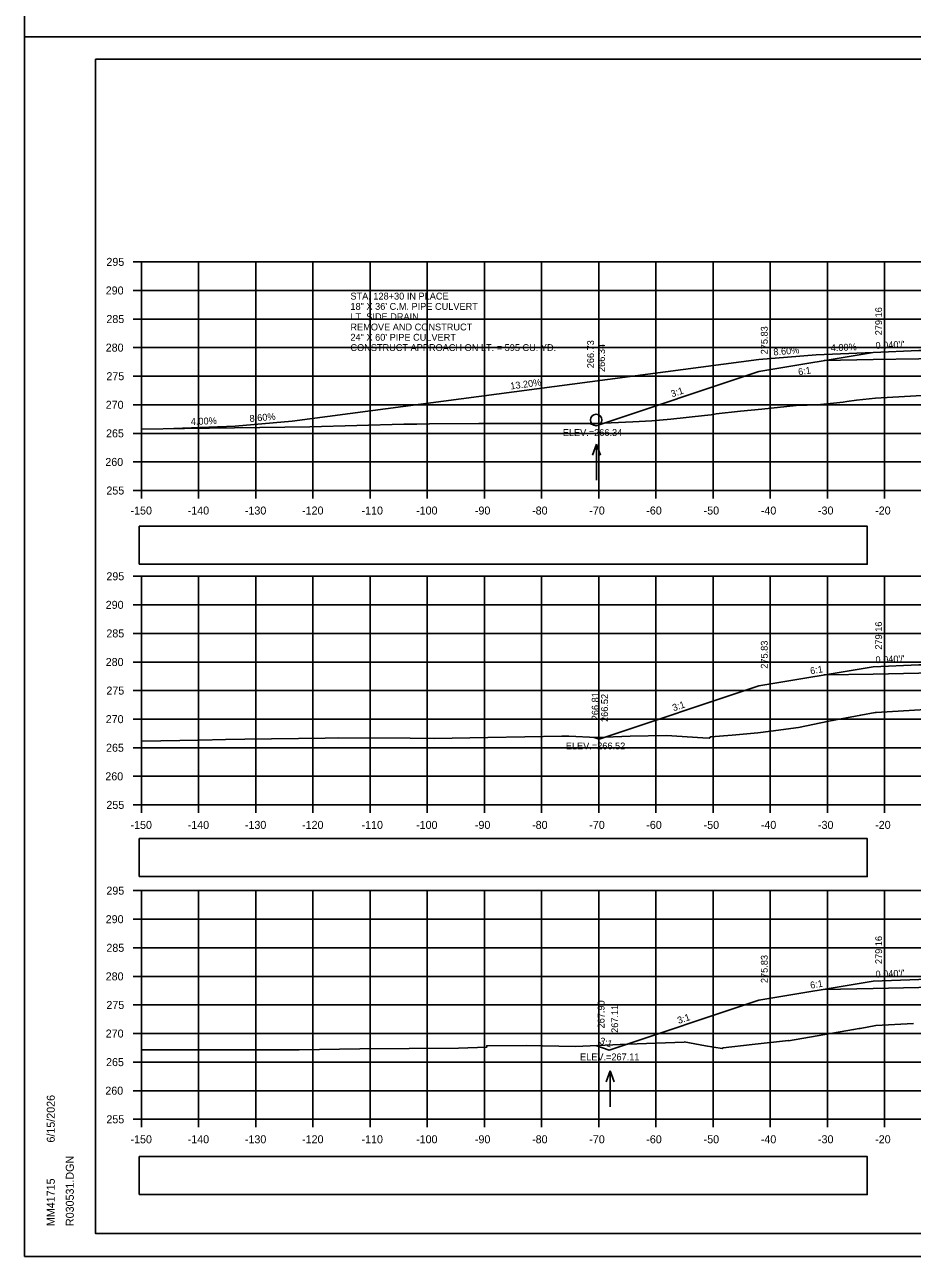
# Model space of a CAD drawing. Extents: x 285 to 4233, y -659 to 3710.
# Drawn here: x 368.9 to 524.1, y 1469.5 to 1685 of the extents above; entities that cross this region are included whole.
import ezdxf

# ---------------------------------------------------------------- set-up
doc = ezdxf.new("R2010")
doc.units = 0
for name, color, linetype in [('R_Alt Surface', 7, 'Continuous'), ('R_Axis', 7, 'Continuous'), ('R_Axis Annot', 7, 'Continuous'), ('R_Border', 7, 'Continuous'), ('R_Drive', 7, 'Continuous'), ('R_Exist Surface', 7, 'Continuous'), ('R_Fin Surface', 7, 'Continuous'), ('R_Grid', 7, 'Continuous'), ('R_No Plot', 7, 'Continuous'), ('R_Water', 7, 'Continuous'), ('R_Water Annot', 7, 'Continuous'), ('R_Xsect Elev', 7, 'Continuous'), ('R_Xsect Slope', 7, 'Continuous')]:
    doc.layers.add(name, color=color, linetype=linetype)

msp = doc.modelspace()

# ---------------------------------------------------------------- linework, layer by layer
at = {"layer": 'R_Alt Surface'}
for points in [[(508.71, 1626.25), (517.28, 1626.42), (525.28, 1626.58), (551.28, 1627.1), (551.28, 1627.1), (557.28, 1626.98), (566.12, 1626.8)], [(508.71, 1571.25), (517.28, 1571.42), (525.28, 1571.58), (551.28, 1572.1), (551.28, 1572.1), (557.28, 1571.98), (566.12, 1571.8)], [(508.71, 1516.25), (517.28, 1516.42), (525.28, 1516.58), (551.28, 1517.1), (551.28, 1517.1), (557.28, 1516.98), (566.12, 1516.8)]]:
    msp.add_lwpolyline(points, dxfattribs=at)
at = {"layer": 'R_Axis'}
for p, q in [((387.88, 1643.52), (389.28, 1643.52)), ((389.28, 1603.52), (389.28, 1643.52)), ((387.88, 1638.52), (389.28, 1638.52)), ((387.88, 1633.52), (389.28, 1633.52)), ((387.88, 1628.52), (389.28, 1628.52)), ((387.88, 1623.52), (389.28, 1623.52)), ((387.88, 1618.52), (389.28, 1618.52)), ((387.88, 1613.52), (389.28, 1613.52)), ((387.88, 1608.52), (389.28, 1608.52)), ((387.88, 1603.52), (389.28, 1603.52)), ((389.28, 1603.52), (689.28, 1603.52)), ((389.28, 1602.12), (389.28, 1603.52)), ((399.28, 1602.12), (399.28, 1603.52)), ((409.28, 1602.12), (409.28, 1603.52)), ((419.28, 1602.12), (419.28, 1603.52)), ((429.28, 1602.12), (429.28, 1603.52)), ((439.28, 1602.12), (439.28, 1603.52)), ((449.28, 1602.12), (449.28, 1603.52)), ((459.28, 1602.12), (459.28, 1603.52)), ((469.28, 1602.12), (469.28, 1603.52)), ((479.28, 1602.12), (479.28, 1603.52)), ((489.28, 1602.12), (489.28, 1603.52)), ((499.28, 1602.12), (499.28, 1603.52)), ((509.28, 1602.12), (509.28, 1603.52)), ((519.28, 1602.12), (519.28, 1603.52)), ((387.88, 1588.52), (389.28, 1588.52)), ((389.28, 1548.52), (389.28, 1588.52)), ((387.88, 1583.52), (389.28, 1583.52)), ((387.88, 1578.52), (389.28, 1578.52)), ((387.88, 1573.52), (389.28, 1573.52)), ((387.88, 1568.52), (389.28, 1568.52)), ((387.88, 1563.52), (389.28, 1563.52)), ((387.88, 1558.52), (389.28, 1558.52)), ((387.88, 1553.52), (389.28, 1553.52)), ((387.88, 1548.52), (389.28, 1548.52)), ((389.28, 1548.52), (689.28, 1548.52)), ((389.28, 1547.12), (389.28, 1548.52)), ((399.28, 1547.12), (399.28, 1548.52)), ((409.28, 1547.12), (409.28, 1548.52)), ((419.28, 1547.12), (419.28, 1548.52)), ((429.28, 1547.12), (429.28, 1548.52)), ((439.28, 1547.12), (439.28, 1548.52)), ((449.28, 1547.12), (449.28, 1548.52)), ((459.28, 1547.12), (459.28, 1548.52)), ((469.28, 1547.12), (469.28, 1548.52)), ((479.28, 1547.12), (479.28, 1548.52)), ((489.28, 1547.12), (489.28, 1548.52)), ((499.28, 1547.12), (499.28, 1548.52)), ((509.28, 1547.12), (509.28, 1548.52)), ((519.28, 1547.12), (519.28, 1548.52)), ((387.88, 1533.52), (389.28, 1533.52)), ((389.28, 1493.52), (389.28, 1533.52)), ((387.88, 1528.52), (389.28, 1528.52)), ((387.88, 1523.52), (389.28, 1523.52)), ((387.88, 1518.52), (389.28, 1518.52)), ((387.88, 1513.52), (389.28, 1513.52)), ((387.88, 1508.52), (389.28, 1508.52)), ((387.88, 1503.52), (389.28, 1503.52)), ((387.88, 1498.52), (389.28, 1498.52)), ((387.88, 1493.52), (389.28, 1493.52)), ((389.28, 1493.52), (689.28, 1493.52)), ((389.28, 1492.12), (389.28, 1493.52)), ((399.28, 1492.12), (399.28, 1493.52)), ((409.28, 1492.12), (409.28, 1493.52)), ((419.28, 1492.12), (419.28, 1493.52)), ((429.28, 1492.12), (429.28, 1493.52)), ((439.28, 1492.12), (439.28, 1493.52)), ((449.28, 1492.12), (449.28, 1493.52)), ((459.28, 1492.12), (459.28, 1493.52)), ((469.28, 1492.12), (469.28, 1493.52)), ((479.28, 1492.12), (479.28, 1493.52)), ((489.28, 1492.12), (489.28, 1493.52)), ((499.28, 1492.12), (499.28, 1493.52)), ((509.28, 1492.12), (509.28, 1493.52)), ((519.28, 1492.12), (519.28, 1493.52))]:
    msp.add_line(p, q, dxfattribs=at)
at = {"layer": 'R_Axis Annot'}
for points in [[(388.91, 1590.62), (516.24, 1590.62), (516.24, 1597.27), (388.91, 1597.27)], [(388.91, 1535.98), (516.24, 1535.98), (516.24, 1542.63), (388.91, 1542.63)], [(388.91, 1480.34), (516.24, 1480.34), (516.24, 1486.99), (388.91, 1486.99)]]:
    msp.add_lwpolyline(points, close=True, dxfattribs=at)
at = {"layer": 'R_Border'}
for p, q in [((381.28, 1678.98), (697.46, 1678.98)), ((381.28, 1473.52), (381.28, 1678.98)), ((381.28, 1473.52), (381.28, 1473.52)), ((697.46, 1473.52), (381.28, 1473.52))]:
    msp.add_line(p, q, dxfattribs=at)
at = {"layer": 'R_Drive'}
for p, q in [((507.28, 1627.28), (497.28, 1626.42)), ((517.28, 1627.68), (507.28, 1627.28)), ((497.28, 1626.42), (415.67, 1615.65)), ((405.67, 1614.79), (394.96, 1614.36)), ((415.67, 1615.65), (405.67, 1614.79))]:
    msp.add_line(p, q, dxfattribs=at)
at = {"layer": 'R_Exist Surface'}
for points in [[(389.28, 1614.28), (396.85, 1614.38), (418.73, 1614.66), (435.21, 1615.12), (437.44, 1615.14), (439.7, 1615.17), (448.33, 1615.26), (458.76, 1615.22), (467.05, 1615.24), (468.95, 1615.26), (475.23, 1615.54), (478.58, 1615.7), (481.91, 1616), (487.79, 1616.64), (488.94, 1616.77), (489.84, 1616.92), (494.07, 1617.39), (497.8, 1617.77), (503.8, 1618.37), (507.68, 1618.54), (508.07, 1618.56), (512, 1618.97), (512.69, 1619.09), (514.35, 1619.31), (517.66, 1619.7), (517.67, 1619.7), (517.68, 1619.7), (526.81, 1620.22)], [(389.28, 1559.67), (399.38, 1559.85), (404.02, 1559.98), (407.39, 1560.02), (421.43, 1560.21), (423.74, 1560.23), (436.27, 1560.22), (440.47, 1560.14), (449.89, 1560.33), (462.85, 1560.57), (463.55, 1560.56), (464.06, 1560.55), (468.87, 1560.31), (474.8, 1560.54), (481.13, 1560.65), (487.47, 1560.23), (488.59, 1560.17), (488.67, 1560.24), (488.9, 1560.45), (492.6, 1560.71), (497.08, 1561.1), (499.37, 1561.44), (504.23, 1562.07), (509.5, 1563.14), (510.45, 1563.35), (511.65, 1563.57), (515.09, 1564.23), (517.64, 1564.67), (517.81, 1564.7), (526.43, 1565.22)], [(389.28, 1505.65), (397.79, 1505.66), (416.86, 1505.69), (427.51, 1505.83), (444.76, 1505.97), (449.68, 1506.15), (449.7, 1506.39), (456.59, 1506.42), (465.16, 1506.26), (474.36, 1506.67), (484.21, 1507.03), (484.22, 1507.06), (487.92, 1506.37), (490.84, 1505.91), (491.06, 1506.02), (496.09, 1506.58), (502.47, 1507.33), (502.49, 1507.26), (513.86, 1509.22), (514.84, 1509.4), (514.84, 1509.39), (514.99, 1509.42), (517.75, 1509.9), (524.35, 1510.26)]]:
    msp.add_lwpolyline(points, dxfattribs=at)
at = {"layer": 'R_Fin Surface'}
for points in [[(467.65, 1615.25), (468.82, 1614.86), (497.28, 1624.35), (517.28, 1627.68), (525.28, 1628), (527.28, 1628.04), (551.28, 1628.52), (557.28, 1628.28), (581.28, 1624.28), (597.77, 1618.78), (608.82, 1622.47)], [(468.46, 1560.33), (469.35, 1560.03), (497.28, 1569.35), (517.28, 1572.68), (525.28, 1573), (527.28, 1573.04), (551.28, 1573.52), (557.28, 1573.28), (581.28, 1569.28), (595.88, 1564.41), (604.59, 1567.31)], [(468.74, 1506.42), (471.12, 1505.63), (497.28, 1514.35), (517.28, 1517.68), (525.28, 1518), (527.28, 1518.04), (551.28, 1518.52), (557.28, 1518.28), (581.28, 1514.28), (589.61, 1511.5), (589.62, 1511.51)]]:
    msp.add_lwpolyline(points, dxfattribs=at)
at = {"layer": 'R_Grid'}
for p, q in [((389.28, 1643.52), (689.28, 1643.52)), ((389.28, 1603.52), (389.28, 1643.52)), ((399.28, 1603.52), (399.28, 1643.52)), ((409.28, 1603.52), (409.28, 1643.52)), ((419.28, 1603.52), (419.28, 1643.52)), ((429.28, 1603.52), (429.28, 1643.52)), ((439.28, 1603.52), (439.28, 1643.52)), ((449.28, 1603.52), (449.28, 1643.52)), ((459.28, 1603.52), (459.28, 1643.52)), ((469.28, 1603.52), (469.28, 1643.52)), ((479.28, 1603.52), (479.28, 1643.52)), ((489.28, 1603.52), (489.28, 1643.52)), ((499.28, 1603.52), (499.28, 1643.52)), ((509.28, 1603.52), (509.28, 1643.52)), ((519.28, 1603.52), (519.28, 1643.52)), ((389.28, 1638.52), (689.28, 1638.52)), ((389.28, 1633.52), (689.28, 1633.52)), ((389.28, 1628.52), (689.28, 1628.52)), ((389.28, 1623.52), (689.28, 1623.52)), ((389.28, 1618.52), (689.28, 1618.52)), ((389.28, 1613.52), (689.28, 1613.52)), ((389.28, 1608.52), (689.28, 1608.52)), ((389.28, 1603.52), (689.28, 1603.52)), ((389.28, 1588.52), (689.28, 1588.52)), ((389.28, 1548.52), (389.28, 1588.52)), ((399.28, 1548.52), (399.28, 1588.52)), ((409.28, 1548.52), (409.28, 1588.52)), ((419.28, 1548.52), (419.28, 1588.52)), ((429.28, 1548.52), (429.28, 1588.52)), ((439.28, 1548.52), (439.28, 1588.52)), ((449.28, 1548.52), (449.28, 1588.52)), ((459.28, 1548.52), (459.28, 1588.52)), ((469.28, 1548.52), (469.28, 1588.52)), ((479.28, 1548.52), (479.28, 1588.52)), ((489.28, 1548.52), (489.28, 1588.52)), ((499.28, 1548.52), (499.28, 1588.52)), ((509.28, 1548.52), (509.28, 1588.52)), ((519.28, 1548.52), (519.28, 1588.52)), ((389.28, 1583.52), (689.28, 1583.52)), ((389.28, 1578.52), (689.28, 1578.52)), ((389.28, 1573.52), (689.28, 1573.52)), ((389.28, 1568.52), (689.28, 1568.52)), ((389.28, 1563.52), (689.28, 1563.52)), ((389.28, 1558.52), (689.28, 1558.52)), ((389.28, 1553.52), (689.28, 1553.52)), ((389.28, 1548.52), (689.28, 1548.52)), ((389.28, 1533.52), (689.28, 1533.52)), ((389.28, 1493.52), (389.28, 1533.52)), ((399.28, 1493.52), (399.28, 1533.52)), ((409.28, 1493.52), (409.28, 1533.52)), ((419.28, 1493.52), (419.28, 1533.52)), ((429.28, 1493.52), (429.28, 1533.52)), ((439.28, 1493.52), (439.28, 1533.52)), ((449.28, 1493.52), (449.28, 1533.52)), ((459.28, 1493.52), (459.28, 1533.52)), ((469.28, 1493.52), (469.28, 1533.52)), ((479.28, 1493.52), (479.28, 1533.52)), ((489.28, 1493.52), (489.28, 1533.52)), ((499.28, 1493.52), (499.28, 1533.52)), ((509.28, 1493.52), (509.28, 1533.52)), ((519.28, 1493.52), (519.28, 1533.52)), ((389.28, 1528.52), (689.28, 1528.52)), ((389.28, 1523.52), (689.28, 1523.52)), ((389.28, 1518.52), (689.28, 1518.52)), ((389.28, 1513.52), (689.28, 1513.52)), ((389.28, 1508.52), (689.28, 1508.52)), ((389.28, 1503.52), (689.28, 1503.52)), ((389.28, 1498.52), (689.28, 1498.52)), ((389.28, 1493.52), (689.28, 1493.52))]:
    msp.add_line(p, q, dxfattribs=at)
at = {"layer": 'R_No Plot'}
for p, q in [((368.88, 1682.88), (702.21, 1682.88)), ((368.88, 1682.87), (702.21, 1682.87)), ((368.88, 1469.54), (702.21, 1469.54))]:
    msp.add_line(p, q, dxfattribs=at)
for points in [[(368.87, 1896.21), (702.21, 1896.21), (702.21, 1682.87), (368.87, 1682.87)], [(368.87, 1682.87), (702.21, 1682.87), (702.21, 1469.54), (368.87, 1469.54)], [(615.2, 1678.98), (634.82, 1678.98), (634.82, 1669.1), (650.93, 1669.1), (674.13, 1669.1), (674.25, 1640.94), (697.46, 1640.94), (697.46, 1473.52), (381.28, 1473.52), (381.28, 1678.98)]]:
    msp.add_lwpolyline(points, close=True, dxfattribs=at)
at = {"layer": 'R_Water'}
msp.add_circle((468.82, 1615.86), 1, dxfattribs=at)
at = {"layer": 'R_Water Annot'}
for p, q in [((468.86, 1611.64), (468.16, 1609.71)), ((468.86, 1605.35), (468.86, 1611.64)), ((468.86, 1611.64), (469.56, 1609.71)), ((471.25, 1502.01), (470.55, 1500.09)), ((471.25, 1495.72), (471.25, 1502.01)), ((471.25, 1502.01), (471.95, 1500.09))]:
    msp.add_line(p, q, dxfattribs=at)

# ---------------------------------------------------------------- texts
at = {"layer": 'R_Axis Annot'}
for s, p in [('295', (383.17, 1642.82)), ('290', (383.05, 1637.82)), ('285', (383.17, 1632.82)), ('280', (383.05, 1627.82)), ('275', (383.17, 1622.82)), ('270', (383.05, 1617.82)), ('265', (383.11, 1612.82)), ('260', (382.98, 1607.82)), ('255', (383.17, 1602.82)), ('-150', (387.39, 1599.32)), ('-140', (397.39, 1599.32)), ('-130', (407.39, 1599.32)), ('-120', (417.39, 1599.32)), ('-110', (427.79, 1599.32)), ('-100', (437.33, 1599.32)), ('-90', (447.62, 1599.32)), ('-80', (457.62, 1599.32)), ('-70', (467.62, 1599.32)), ('-60', (477.59, 1599.32)), ('-50', (487.62, 1599.32)), ('-40', (497.62, 1599.32)), ('-30', (507.62, 1599.32)), ('-20', (517.62, 1599.32)), ('295', (383.17, 1587.82)), ('290', (383.05, 1582.82)), ('285', (383.17, 1577.82)), ('280', (383.05, 1572.82)), ('275', (383.17, 1567.82)), ('270', (383.05, 1562.82)), ('265', (383.11, 1557.82)), ('260', (382.98, 1552.82)), ('255', (383.17, 1547.82)), ('-150', (387.39, 1544.32)), ('-140', (397.39, 1544.32)), ('-130', (407.39, 1544.32)), ('-120', (417.39, 1544.32)), ('-110', (427.79, 1544.32)), ('-100', (437.33, 1544.32)), ('-90', (447.62, 1544.32)), ('-80', (457.62, 1544.32)), ('-70', (467.62, 1544.32)), ('-60', (477.59, 1544.32)), ('-50', (487.62, 1544.32)), ('-40', (497.62, 1544.32)), ('-30', (507.62, 1544.32)), ('-20', (517.62, 1544.32)), ('295', (383.17, 1532.82)), ('290', (383.05, 1527.82)), ('285', (383.17, 1522.82)), ('280', (383.05, 1517.82)), ('275', (383.17, 1512.82)), ('270', (383.05, 1507.82)), ('265', (383.11, 1502.82)), ('260', (382.98, 1497.82)), ('255', (383.17, 1492.82)), ('-150', (387.39, 1489.32)), ('-140', (397.39, 1489.32)), ('-130', (407.39, 1489.32)), ('-120', (417.39, 1489.32)), ('-110', (427.79, 1489.32)), ('-100', (437.33, 1489.32)), ('-90', (447.62, 1489.32)), ('-80', (457.62, 1489.32)), ('-70', (467.62, 1489.32)), ('-60', (477.59, 1489.32)), ('-50', (487.62, 1489.32)), ('-40', (497.62, 1489.32)), ('-30', (507.62, 1489.32)), ('-20', (517.62, 1489.32))]:
    msp.add_text(s, height=1.4, dxfattribs=at).set_placement(p)
at = {"layer": 'R_Border'}
for s, p in [('6/15/2026', (374.14, 1489.45)), ('R030531.DGN', (377.47, 1474.84)), ('MM41715', (374.14, 1474.84))]:
    msp.add_text(s, height=1.4, rotation=90, dxfattribs=at).set_placement(p)
at = {"layer": 'R_Water Annot'}
for s, p in [('STA. 128+30 IN PLACE', (425.85, 1636.93)), ('18" X 36\' C.M. PIPE CULVERT', (425.85, 1635.13)), ('LT. SIDE DRAIN', (425.85, 1633.33)), ('REMOVE AND CONSTRUCT', (425.85, 1631.53)), ('24" X 60\' PIPE CULVERT', (425.85, 1629.73)), ('CONSTRUCT APPROACH ON LT. = 595 CU. YD.', (425.85, 1627.93))]:
    msp.add_text(s, height=1.2, dxfattribs=at).set_placement(p)
at = {"layer": 'R_Xsect Elev'}
for s, rotation, p in [('279.16', 90, (518.83, 1630.68)), ('275.83', 90, (498.83, 1627.35)), ('266.73', 90, (468.45, 1624.91)), ('4.00%', 2.2906, (509.87, 1627.88)), ('266.34', 90, (470.37, 1624.26)), ('8.60%', 4.9153, (499.87, 1627.14)), ('13.20%', 7.5196, (453.89, 1621.19)), ('4.00%', 2.2906, (397.95, 1614.98)), ('8.60%', 4.9153, (408.26, 1615.51)), ('279.16', 90, (518.83, 1575.68)), ('275.83', 90, (498.83, 1572.35)), ('266.81', 90, (469.26, 1563.33)), ('266.52', 90, (470.9, 1563.03)), ('279.16', 90, (518.83, 1520.68)), ('275.83', 90, (498.83, 1517.35)), ('267.90', 90, (470.29, 1509.42)), ('267.11', 90, (472.67, 1508.63))]:
    msp.add_text(s, height=1.2, rotation=rotation, dxfattribs=at).set_placement(p)
for s, p in [('ELEV.=266.34', (462.99, 1613.06)), ('ELEV.=266.52', (463.52, 1558.23)), ('ELEV.=267.11', (466, 1503.83))]:
    msp.add_text(s, height=1.2, dxfattribs=at).set_placement(p)
at = {"layer": 'R_Xsect Slope'}
for s, rotation, p in [("0.040'/'", 2.2906, (517.7, 1628.3)), ('6:1', 9.4623, (504.25, 1623.65)), ('3:1', 18.4349, (482.1, 1619.81)), ("0.040'/'", 2.2906, (517.7, 1573.3)), ('6:1', 9.4623, (506.35, 1571.36)), ('3:1', 18.4349, (482.37, 1564.9)), ("0.040'/'", 2.2906, (517.7, 1518.3)), ('6:1', 9.4623, (506.35, 1516.36)), ('3:1', 18.4349, (483.25, 1510.2)), ('3:1', 341.5651, (469.3, 1506.76))]:
    msp.add_text(s, height=1.2, rotation=rotation, dxfattribs=at).set_placement(p)

doc.saveas('drawing.dxf')
